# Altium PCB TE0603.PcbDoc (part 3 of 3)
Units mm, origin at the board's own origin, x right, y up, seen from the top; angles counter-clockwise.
Board outline 115 x 70 mm, 4 copper layers (L 01 (Top), L 02, L 03, L 04 (Bot)), stack 1.564 mm thick; 86 components, 166 nets, 587 pads, 211 vias.
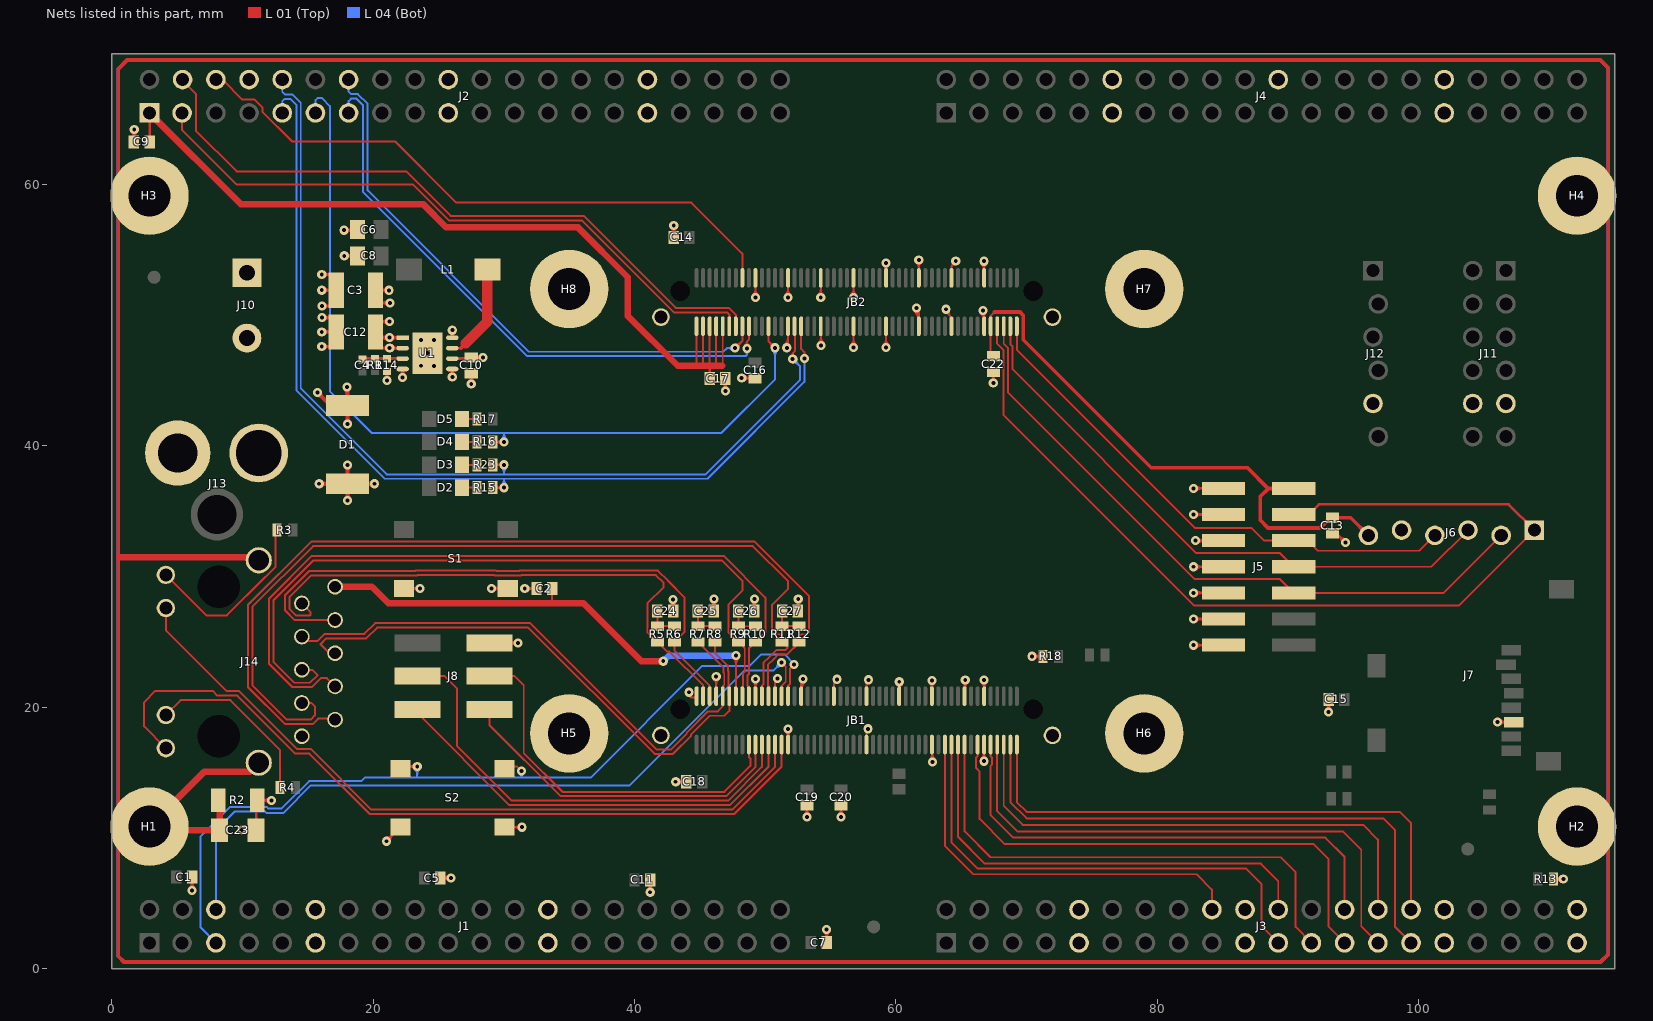
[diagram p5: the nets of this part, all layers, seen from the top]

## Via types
v1: diameter 0.7, hole 0.3, L 01 (Top) to L 04 (Bot), 211 vias

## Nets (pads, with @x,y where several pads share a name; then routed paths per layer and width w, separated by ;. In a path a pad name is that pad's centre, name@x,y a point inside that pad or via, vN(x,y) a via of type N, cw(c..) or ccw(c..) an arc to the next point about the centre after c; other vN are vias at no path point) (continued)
B2B_B3_L9_P: J2.11 JB2.24 R16.2 | length 70.9
  L 01 (Top) w0.15: R16.2@29.15,40.3 v1(30.025,40.3) ; v1@29.831,40.106 ccw(c29.361,39.636) 29.361,40.3 ccw(c29.361,40.964) v1@29.831,40.494 ; JB2.24@50.25,48.85 50.25,48.005 v1(50.752,47.502) ; v1@50.477,47.502 ccw(c49.814,47.502) 50.283,47.972 ccw(c50.752,48.441) v1@50.752,47.777
  L 04 (Bot) w0.15: J2.11@15.591,65.479 15.591,66.441 15.75,66.6 16.1,66.6 16.7,66 16.7,44.17 19.885,40.985 46.641,40.985 50.752,45.097 v1(50.752,47.502) ; v1@29.831,40.495 ccw(c29.371,40.96) 30.025,40.96 ; v1(30.025,40.3) 30.025,40.96 ; v1@30.219,40.495 cw(c30.679,40.96) 30.025,40.96 ; v1@50.558,47.308 cw(c50.089,46.838) 50.752,46.838 cw(c51.416,46.838) v1@50.947,47.308
B2B_B3_L59_N: J2.9 JB2.34 R15.2 | length 77.1
  L 01 (Top) w0.15: R15.2@29.15,36.8 v1(30.025,36.8) ; v1@29.831,36.606 ccw(c29.361,36.136) 29.361,36.8 ccw(c29.361,37.464) v1@29.831,36.994 ; JB2.34@52.75,48.85 52.75,47.425 53.003,47.172 ; v1@52.857,46.911 ccw(c52.694,47.172) 53.003,47.172 ; v1(53.003,46.677) 53.003,47.172 ; v1@53.148,46.911 cw(c53.311,47.172) 53.003,47.172
  L 04 (Bot) w0.15: J2.9@13.051,65.479 13.051,66.351 13.25,66.55 13.669,66.55 14.125,66.094 14.125,44.25 20.89,37.485 30.025,37.485 ; v1@29.831,36.994 ccw(c29.361,37.464) 30.025,37.464 ccw(c30.689,37.464) v1@30.219,36.994 ; v1(30.025,36.8) 30.025,37.485 ; v1(53.003,46.677) 53.003,44.903 45.585,37.485 30.025,37.485
B2B_B3_L59_P: J2.10 JB2.32 R23.2 | length 77.9
  L 01 (Top) w0.15: R23.2@29.15,38.55 v1(30.025,38.55) ; v1@29.831,38.356 ccw(c29.361,37.886) 29.361,38.55 ccw(c29.361,39.214) v1@29.831,38.744 ; v1@51.987,46.902 ccw(c51.903,47.083) 52.103,47.083 ; v1@52.218,46.902 cw(c52.302,47.083) 52.103,47.083 ; JB2.32@52.25,48.85 52.268,48.833 52.268,47.248 52.103,47.083 ; v1@52.103,46.753 v1(52.103,46.652) 52.098,46.652 52.05,46.7 v1@52.103,46.753 ; v1@52.103,46.753 52.103,47.083
  L 04 (Bot) w0.15: J2.10@13.051,68.019 13.051,67.089 13.25,66.89 13.81,66.89 14.465,66.235 14.465,44.39 21.031,37.825 45.444,37.825 52.65,45.031 52.65,46.105 v1(52.103,46.652) ; v1@29.831,38.356 cw(c29.361,37.886) 30.025,37.886 cw(c30.689,37.886) v1@30.219,38.356 ; 30.025,37.85 v1(30.025,38.55) ; v1@52.103,46.377 cw(c52.103,45.713) 52.572,46.183 cw(c53.041,46.652) v1@52.378,46.652
B2B_B3_L60_N: J2.14 JB2.16 | length 46.3
  L 01 (Top) w0.15: v1@47.7,47.75 ccw(c47.7,48.427) 48.178,47.948 ; v1@47.935,47.705 48.25,48.02 JB2.16@48.25,48.85 ; v1@47.975,47.475 cw(c48.626,47.475) 48.166,47.935
  L 04 (Bot) w0.15: J2.14@18.131,68.019 18.131,67.109 18.325,66.915 18.841,66.915 19.575,66.181 19.575,59.55 31.925,47.2 46.8,47.2 47.075,47.475 ; v1@47.497,47.289 ccw(c47.075,46.902) 47.075,47.475 ; v1@47.497,47.661 cw(c47.075,48.048) 47.075,47.475 ; v1@47.7,47.552 47.852,47.552 47.775,47.475 v1(47.7,47.475) 47.075,47.475
B2B_B3_L60_P: J2.13 JB2.18 | length 46.8
  L 01 (Top) w0.15: v1@48.447,47.68 ccw(c48.248,47.973) 48.602,47.973 ; v1(48.602,47.452) 48.602,47.973 ; JB2.18@48.75,48.85 48.75,48.121 48.602,47.973 ; v1@48.757,47.68 cw(c48.957,47.973) 48.602,47.973
  L 04 (Bot) w0.15: J2.13@18.131,65.479 18.131,66.381 18.325,66.575 18.7,66.575 19.235,66.04 19.235,59.409 31.784,46.86 48.51,46.86 48.602,46.952 ; v1@48.455,47.22 cw(c48.285,46.952) 48.602,46.952 ; v1(48.602,47.452) 48.602,46.952 ; v1@48.75,47.22 ccw(c48.919,46.952) 48.602,46.952
B2B_PROGB: J2.3 JB2.12 | length 50.2
  L 01 (Top) w0.15: J2.3@5.391,65.449 5.391,64.148 9.538,60 23.046,60 25.796,57.25 35.884,57.25 35.969,57.25 43.009,50.21 47.084,50.21 47.25,50.044 JB2.12@47.25,49.15 ; JB2.12@47.25,48.85 JB2.12@47.25,49.15
CCLK: J3.26 JB1.92 | length 37.8
  L 01 (Top) w0.15: JB1.92@67.25,17.05 67.25,16.235 67.355,16.13 67.355,15.62 67.25,15.515 67.25,11.75 68.975,10.025 92.85,10.025 94.331,8.544 J3.26@94.331,4.519
CSO_B: J3.25 JB1.88 | length 40.6
  L 01 (Top) w0.15: JB1.88@66.25,17.05 66.25,16.255 66.125,16.13 66.125,15.355 66.4,15.08 66.4,11.46 68.335,9.525 91.95,9.525 93.1,8.375 93.1,3.21 J3.25@94.331,1.979
EN: J1.6 JB1.27 | length 58.7
  L 01 (Top) w0.15: JB1.27@51.25,20.75 51.25,21.631 51.57,21.95 51.57,23.105 v1(51.25,23.425)
  L 04 (Bot) w0.15: J1.6@7.971,4.519 7.971,10.571 9.425,12.025 11.726,12.025 11.83,11.921 13.146,11.921 15.243,14.017 39.631,14.017 48.438,22.825 50.65,22.825 v1(51.25,23.425) ; v1@50.975,23.425 cw(c50.311,23.425) 50.781,22.956 cw(c51.25,22.486) v1@51.25,23.15
FGND: C23.1 H1.1 H2.1 H3.1 H4.1 J14.15 J14.16 R2.1 | length 758.1
  L 01 (Top) w0.3: 0.501,0.949 0.501,68.824 1.186,69.509 113.891,69.509 114.501,68.899 114.501,1.099 113.901,0.499 0.951,0.499 0.501,0.949
  L 01 (Top) w0.5: 0.596,31.475 J14.15@11.25,31.475 ; R2.1@8.15,12.9 8.25,12.8 C23.1@8.25,10.6 3.16,10.6 H1.1@2.891,10.869 7.071,15.05 10.545,15.05 J14.16@11.25,15.755
  L 04 (Bot) w0.3: 0.501,0.949 0.501,68.824 1.176,69.499 113.901,69.499 114.501,68.899 114.501,1.099 113.901,0.499 0.951,0.499 0.501,0.949
GND: C1.2 C2.1 C3.1 C5.2 C6.2 C7.2 C8.2 C9.2 C10.2 C11.2 C12.1 C13.2 C14.2 C15.2 C16.2 C17.2 C18.1 C19.1 C20.1 C22.2 C23.2 C24.2 C25.2 C26.2 C27.2 D1.2 H5.1 H6.1 H7.1 H8.1 J1.11 J1.12 J1.25 J1.26 J2.8 J2.19 J2.20 J2.31 J2.32 J3.9 J3.10 J3.19 J3.20 J3.31 J3.32 J3.39 J3.40 J4.11 J4.12 J4.22 J4.31 J4.32 J5.1 J5.3 J5.5 J5.7 J5.9 J5.11 J5.13 J6.5 J7.6 J8.2 J10.2 J11.9 J11.10 J12.5 J13.3 J14.10 JB1.1 JB1.7 JB1.19 JB1.25 JB1.30 JB1.33 JB1.43 JB1.53 JB1.54 JB1.63 JB1.73 JB1.74 JB1.83 JB1.89 JB1.90 JB1.F1 JB1.F2 JB2.19 JB2.29 JB2.30 JB2.39 JB2.40 JB2.49 JB2.50 JB2.59 JB2.60 JB2.69 JB2.70 JB2.79 JB2.80 JB2.89 JB2.90 JB2.F1 JB2.F2 R2.2 R13.2 R14.2 R18.1 S1.2 S2.2 U1.4 U1.5 U1.8 U1.9 | length 194.1
  L 01 (Top) w0.15: v1(21.025,9.75) S2.2@22.1,10.825 ; v1@21.025,10.025 ccw(c21.025,10.689) 21.494,10.219 ccw(c21.964,9.75) v1@21.3,9.75 ; S1.2@22.355,29.1 v1(23.6,29.1) ; v1@23.406,28.906 ccw(c22.936,28.436) 22.936,29.1 ccw(c22.936,29.764) v1@23.406,29.294 ; C5.2@25.125,6.925 v1(25.95,6.925) ; v1@25.756,6.731 ccw(c25.286,6.261) 25.286,6.925 ccw(c25.286,7.589) v1@25.756,7.119 ; J8.2@28.9,24.915 v1(31.09,24.915) ; v1(29.05,29.1) S1.2@30.305,29.1 ; v1@29.244,28.906 cw(c29.714,28.436) 29.714,29.1 cw(c29.714,29.764) v1@29.244,29.294 ; S2.2@30.05,10.825 v1(31.4,10.825) ; v1@30.896,24.721 ccw(c30.426,24.251) 30.426,24.915 ccw(c30.426,25.579) v1@30.896,25.109 ; v1@31.206,10.631 ccw(c30.736,10.161) 30.736,10.825 ccw(c30.736,11.489) v1@31.206,11.019 ; v1(31.6,29.075) C2.1@32.5,29.075 ; v1@31.794,28.881 cw(c32.264,28.411) 32.264,29.075 cw(c32.264,29.739) v1@31.794,29.269 ; v1(44.175,21.15) 44.054,21.15 43.944,21.04 44.01,21.04 44.3,20.75 JB1.1@44.75,20.75 ; v1@46.056,22.155 cw(c45.586,21.686) 46.25,21.686 cw(c46.914,21.686) v1@46.445,22.155 ; JB1.7@46.25,20.75 v1(46.25,22.35) ; v1@49.056,21.981 cw(c48.585,21.51) JB1.19@49.25,21.51 ; v1@49.056,51.545 ccw(c48.586,52.014) 49.25,52.014 ccw(c49.914,52.014) v1@49.445,51.545 ; JB1.19@49.25,20.75 49.25,22 v1(49.25,22.175) ; JB1.19@49.25,21.512 cw(c49.913,21.512) v1@49.444,21.981 ; v1(49.25,51.35) JB2.19@49.25,52.55 ; JB1.25@50.75,20.525 JB1.25@50.75,20.75 ; JB1.25@50.75,20.75 50.75,22 v1(50.95,22.2) ; v1@51.458,47.697 ccw(c50.753,48.402) JB2.30@51.75,48.402 ; v1@51.556,18.156 cw(c51.085,17.685) JB1.30@51.75,17.685 ; v1@51.556,51.545 ccw(c51.086,52.014) 51.75,52.014 ccw(c52.414,52.014) v1@51.945,51.545 ; v1@51.564,47.591 ccw(c51.115,48.04) 51.75,48.04 ; v1(51.653,47.502) 51.75,47.6 JB2.30@51.75,48.85 ; JB1.30@51.75,17.05 v1@51.75,18.191 ; JB1.30@51.75,17.687 cw(c52.413,17.687) v1@51.944,18.156 ; 51.75,47.93 ccw(c52.08,47.93) v1@51.847,47.697 ; v1(51.75,51.35) JB2.29@51.75,52.55 ; v1@52.683,21.957 cw(c52.521,21.795) 52.75,21.795 ; JB1.33@52.75,20.75 52.75,22.024 v1(52.878,22.151) ; JB1.33@52.75,21.18 cw(c53.849,21.18) v1@53.072,21.957 ; JB1.33@52.75,21.542 cw(c53.487,21.542) v1@52.966,22.063 ; v1@53.006,11.794 ccw(c52.536,12.264) 53.2,12.264 ccw(c53.864,12.264) v1@53.394,11.794 ; v1(53.2,11.6) C19.1@53.2,12.5 ; v1@54.056,51.545 ccw(c53.586,52.014) 54.25,52.014 ccw(c54.914,52.014) v1@54.445,51.545 ; v1@54.083,47.872 ccw(c53.68,48.275) 54.25,48.275 ; v1@54.25,47.705 JB2.40@54.25,48.85 ; 54.25,48.045 ccw(c54.646,48.045) v1@54.366,47.766 ; JB2.40@54.25,48.407 ccw(c55.008,48.407) v1@54.472,47.872 ; v1(54.25,51.35) JB2.39@54.25,52.55 ; JB1.43@55.25,20.75 55.25,21.85 55.35,21.95 55.315,21.985 55.315,21.991 55.464,22.14 v1(55.499,22.14) ; v1@55.606,11.794 ccw(c55.136,12.264) 55.8,12.264 ccw(c56.464,12.264) v1@55.994,11.794 ; v1(55.8,11.6) C20.1@55.8,12.5 ; v1@56.556,47.719 ccw(c56.085,48.19) 56.75,48.19 ; v1@56.556,51.545 ccw(c56.086,52.014) 56.75,52.014 ccw(c57.414,52.014) v1@56.945,51.545 ; v1(56.75,47.525) JB2.50@56.75,48.85 ; 56.75,48.188 ccw(c57.413,48.188) v1@56.944,47.719 ; v1(56.75,51.35) JB2.49@56.75,52.55 ; JB1.54@57.75,17.05 57.75,18.191 57.783,18.225 57.853,18.225 v1(57.853,18.351) ; JB1.53@57.75,20.75 57.75,21.849 57.903,22.001 57.929,22.001 57.929,22.071 57.903,22.097 v1(57.903,22.101) ; v1@59.056,47.719 ccw(c58.585,48.19) 59.25,48.19 ; v1@59.058,53.808 cw(c58.595,53.345) JB2.59@59.25,53.345 ; v1(59.25,47.525) JB2.60@59.25,48.85 ; 59.25,48.188 ccw(c59.913,48.188) v1@59.444,47.719 ; JB2.59@59.25,52.55 59.25,53.75 59.25,54.197 59.253,54.197 v1(59.253,54.003) ; JB2.59@59.25,53.332 cw(c59.923,53.332) v1@59.447,53.808 ; v1@60.058,21.757 cw(c59.596,21.294) JB1.63@60.25,21.294 ; JB1.63@60.25,20.75 60.25,22.025 60.325,22.1 v1@60.35,22.075 ; JB1.63@60.25,21.281 cw(c60.923,21.281) v1@60.447,21.757 ; v1(60.253,21.951) 60.253,21.947 60.275,21.925 60.327,21.925 60.378,21.976 60.374,21.976 60.374,22.075 60.477,22.075 60.503,22.101 v1@60.499,22.101 ; v1@61.381,50.356 cw(c60.489,49.464) JB2.70@61.75,49.464 ; v1@61.487,50.462 cw(c60.851,49.826) JB2.70@61.75,49.826 ; v1@61.556,54.031 cw(c61.086,53.561) 61.75,53.561 cw(c62.414,53.561) v1@61.944,54.031 ; v1(61.575,50.55) 61.75,50.375 JB2.70@61.75,49.15 ; v1@61.593,50.568 cw(c61.213,50.188) 61.75,50.188 ; JB2.70@61.75,48.85 61.75,49.975 ; JB2.69@61.75,52.55 JB2.69@61.75,52.85 v1(61.75,54.225) ; v1@62.556,21.855 cw(c62.086,21.386) 62.75,21.386 cw(c63.414,21.386) v1@62.945,21.855 ; v1@62.606,16.019 ccw(c62.256,16.369) 62.75,16.369 ; 62.75,16.247 ccw(c63.222,16.247) v1@62.888,15.913 ; JB1.74@62.75,16.609 ccw(c63.584,16.609) v1@62.994,16.019 ; JB1.74@62.75,17.05 62.75,15.958 62.8,15.908 v1(62.8,15.825) ; JB1.73@62.75,20.75 v1(62.75,22.05) ; v1@63.828,50.177 cw(c63.828,49.981) 63.967,50.12 ; v1(63.828,50.452) 63.828,50.182 63.845,50.165 63.922,50.165 64.25,49.837 JB2.80@64.25,48.85 ; v1@63.942,50.401 ccw(c64.198,50.286) 64,50.087 ; v1@64.079,50.34 ccw(c64.41,50.191) 64.153,49.933 ; JB2.79@64.25,52.55 64.25,53.75 64.451,53.95 64.575,53.95 64.578,53.953 v1(64.578,54.153) ; v1@64.33,54.034 cw(c64.135,53.941) 64.288,53.787 cw(c64.514,53.561) v1@64.549,53.879 ; v1@65.109,21.882 cw(c64.767,21.54) JB1.83@65.25,21.54 ; JB1.83@65.25,20.75 65.25,22.075 v1(65.303,22.076) ; JB1.83@65.25,21.284 cw(c66.095,21.284) v1@65.498,21.882 ; 65.25,21.647 cw(c65.733,21.647) v1@65.392,21.988 ; v1@66.459,50.158 cw(c65.755,49.454) JB2.90@66.75,49.454 ; v1@66.534,53.933 cw(c66.011,53.411) JB2.89@66.75,53.411 ; v1@66.546,16.069 ccw(c66.051,16.564) JB1.90@66.75,16.564 ; v1@66.556,21.881 cw(c66.086,21.411) 66.75,21.411 cw(c67.414,21.411) v1@66.945,21.881 ; v1@66.565,50.264 cw(c66.117,49.816) JB2.90@66.75,49.816 ; v1@66.64,54.039 cw(c66.373,53.773) 66.75,53.773 ; v1(66.653,50.352) 66.653,50.302 66.578,50.227 66.598,50.227 66.75,50.075 JB2.90@66.75,48.85 ; v1(66.728,54.128) 66.75,54.106 66.75,53.75 ; v1@66.75,15.885 JB1.90@66.75,17.05 ; JB1.90@66.75,16.514 ccw(c67.379,16.514) v1@66.934,16.069 ; JB1.89@66.75,20.75 v1(66.75,22.075) ; 66.75,49.923 cw(c67.083,49.923) v1@66.848,50.158 ; JB2.89@66.75,52.55 66.75,53.75 ; JB2.89@66.75,53.517 cw(c67.339,53.517) v1@66.923,53.933 ; v1@67.256,44.994 ccw(c66.786,45.464) 67.45,45.464 ccw(c68.114,45.464) v1@67.644,44.994 ; v1(67.45,44.8) C22.2@67.45,45.65 ; 66.75,53.749 cw(c66.885,53.749) 66.833,53.874 ccw(c66.884,53.749) 66.75,53.749 ; 66.75,53.749 ccw(c66.636,53.749) 66.663,53.861 cw(c66.636,53.749) 66.75,53.749
  L 01 (Top) w0.2: v1@1.548,64.033 cw(c1.182,63.666) C9.2@1.7,63.666 ; C9.2@1.7,63.25 1.7,64.184 v1(1.725,64.209) ; C9.2@1.7,63.546 cw(c2.389,63.546) v1@1.902,64.033 ; v1@5.973,6.152 ccw(c5.546,6.579) 6.15,6.579 ccw(c6.754,6.579) v1@6.327,6.152 ; v1(6.15,5.975) C1.2@6.15,7 ; v1(9.95,10.6) C23.2@11.05,10.6 11.05,12.8 R2.2@11.15,12.9 12.25,12.9 v1(12.226,12.876) ; v1@10.127,10.423 cw(c10.554,9.996) 10.554,10.6 cw(c10.554,11.204) v1@10.127,10.777 ; R2.2@11.563,12.9 cw(c11.563,12.213) v1@12.049,12.699 ; R2.2@11.681,12.9 ccw(c11.681,13.42) v1@12.049,13.052 ; v1(16.07,47.6) C12.1@17.1,47.6 ; v1(16.07,48.72) C12.1@17.1,48.72 ; v1(16.07,51.91) C3.1@17.1,51.91 ; v1(16.07,53.11) C3.1@17.1,53.11 ; v1(16.08,49.81) C12.1@17.11,49.81 ; v1(16.08,50.7) C3.1@17.11,50.7 ; v1@16.247,47.423 cw(c16.674,46.996) 16.674,47.6 cw(c16.674,48.204) v1@16.247,47.777 ; v1@16.247,48.543 cw(c16.674,48.116) 16.674,48.72 cw(c16.674,49.324) v1@16.247,48.897 ; v1@16.247,51.733 cw(c16.674,51.306) 16.674,51.91 cw(c16.674,52.514) v1@16.247,52.087 ; v1@16.247,52.933 cw(c16.674,52.506) 16.674,53.11 cw(c16.674,53.714) v1@16.247,53.287 ; v1@16.257,49.633 cw(c16.684,49.206) 16.684,49.81 cw(c16.684,50.414) v1@16.257,49.987 ; v1@16.257,50.523 cw(c16.684,50.096) 16.684,50.7 cw(c16.684,51.304) v1@16.257,50.877 ; v1(17.77,56.5) C6.2@18.8,56.5 ; v1(17.79,54.54) C8.2@18.82,54.54 ; v1@17.947,56.323 cw(c18.374,55.896) 18.374,56.5 cw(c18.374,57.104) v1@17.947,56.677 ; v1@17.967,54.363 cw(c18.394,53.936) 18.394,54.54 cw(c18.394,55.144) v1@17.967,54.717 ; v1@20.883,45.187 ccw(c20.456,45.614) 21.06,45.614 ccw(c21.664,45.614) v1@21.237,45.187 ; v1(21.06,45.01) R14.2@21.06,45.7 ; v1@22.083,45.397 ccw(c21.656,45.824) 22.26,45.824 ccw(c22.864,45.824) v1@22.437,45.397 ; v1(22.26,45.22) 22.26,45.32 U1.4@22.26,45.88 ; v1@25.883,45.437 ccw(c25.456,45.864) 26.06,45.864 ccw(c26.664,45.864) v1@26.237,45.437 ; v1@25.891,48.666 cw(c25.535,48.28) U1.8@26.06,48.28 ; v1(26.06,45.26) U1.5@26.06,45.88 ; v1(26.06,48.85) U1.8@26.06,48.28 ; v1@26.229,48.666 ccw(c26.585,48.28) U1.8@26.06,48.28 ; v1@27.333,44.917 ccw(c26.906,45.344) 27.51,45.344 ccw(c28.114,45.344) v1@27.687,44.917 ; v1(27.51,44.74) C10.2@27.51,45.56 ; v1@41.023,6.027 ccw(c40.596,6.454) 41.2,6.454 ccw(c41.804,6.454) v1@41.377,6.027 ; v1(41.2,5.85) C11.2@41.2,6.8 ; v1@42.773,28.073 cw(c42.346,27.646) 42.95,27.646 cw(c43.554,27.646) v1@43.127,28.073 ; v1@42.823,56.693 cw(c42.396,56.266) 43,56.266 cw(c43.604,56.266) v1@43.177,56.693 ; C24.2@42.95,27.35 v1(42.95,28.25) ; C14.2@43,55.95 v1(43,56.87) ; v1(43.15,14.3) C18.1@43.975,14.3 ; v1@43.327,14.123 cw(c43.754,13.696) 43.754,14.3 cw(c43.754,14.904) v1@43.327,14.477 ; v1@45.898,28.098 cw(c45.532,27.732) C25.2@46.05,27.732 ; C25.2@46.05,27.35 46.05,28.25 v1(46.075,28.275) ; C25.2@46.05,27.611 cw(c46.739,27.611) v1@46.252,28.098 ; v1@46.773,44.377 ccw(c46.346,44.804) 46.95,44.804 ccw(c47.554,44.804) v1@47.127,44.377 ; v1(46.95,44.2) C17.2@46.95,45.15 ; v1(48.2,45.2) 48.225,45.175 C16.2@49.225,45.175 ; v1@48.377,45.023 cw(c48.743,44.657) C16.2@48.743,45.175 ; v1@48.377,45.377 ccw(c48.864,45.864) C16.2@48.864,45.175 ; v1@48.998,28.098 cw(c48.632,27.732) C26.2@49.15,27.732 ; C26.2@49.15,27.35 49.15,28.25 v1(49.175,28.275) ; C26.2@49.15,27.611 cw(c49.839,27.611) v1@49.352,28.098 ; v1@51.59,47.565 51.527,47.502 v1(51.653,47.502) ; v1@52.348,28.098 cw(c51.982,27.732) C27.2@52.5,27.732 ; C27.2@52.5,27.35 52.5,28.25 v1(52.525,28.275) ; C27.2@52.5,27.611 cw(c53.189,27.611) v1@52.702,28.098 ; v1@54.25,47.705 v1(54.278,47.677) ; v1@54.523,2.823 cw(c54.096,2.396) 54.7,2.396 cw(c55.304,2.396) v1@54.877,2.823 ; C7.2@54.7,2 v1(54.7,3) ; v1(66.74,15.875) v1@66.75,15.885 ; v1(70.42,23.9) R18.1@71.25,23.9 ; v1@70.597,23.723 cw(c71.024,23.296) 71.024,23.9 cw(c71.024,24.504) v1@70.597,24.077 ; v1(82.775,24.75) J5.13@85.065,24.75 ; v1(82.775,26.75) J5.11@85.065,26.75 ; v1(82.775,28.75) J5.9@85.065,28.75 ; v1(82.775,30.75) J5.7@85.065,30.75 ; v1(82.775,34.75) J5.3@85.065,34.75 ; v1(82.775,36.75) J5.1@85.065,36.75 ; v1(82.91,32.75) J5.5@85.2,32.75 ; v1@82.952,24.573 cw(c83.379,24.146) 83.379,24.75 cw(c83.379,25.354) v1@82.952,24.927 ; v1@82.952,26.573 cw(c83.379,26.146) 83.379,26.75 cw(c83.379,27.354) v1@82.952,26.927 ; v1@82.952,28.573 cw(c83.379,28.146) 83.379,28.75 cw(c83.379,29.354) v1@82.952,28.927 ; v1@82.952,30.573 cw(c83.379,30.146) 83.379,30.75 cw(c83.379,31.354) v1@82.952,30.927 ; v1@82.952,34.573 cw(c83.379,34.146) 83.379,34.75 cw(c83.379,35.354) v1@82.952,34.927 ; v1@82.952,36.573 cw(c83.379,36.146) 83.379,36.75 cw(c83.379,37.354) v1@82.952,36.927 ; v1@83.087,32.573 cw(c83.514,32.146) 83.514,32.75 cw(c83.514,33.354) v1@83.087,32.927 ; v1@92.923,19.827 ccw(c92.496,20.254) 93.1,20.254 ccw(c93.704,20.254) v1@93.277,19.827 ; v1(93.1,19.65) C15.2@93.1,20.6 ; C13.2@93.4,33.3 93.7,33.3 v1(94.4,32.6) ; v1@94.15,32.6 ccw(c93.546,32.6) 93.973,33.027 ccw(c94.4,33.454) v1@94.4,32.85 ; v1(106.025,18.875) 106.035,18.865 J7.6@107.275,18.865 ; v1@106.202,18.698 cw(c106.604,18.296) J7.6@106.604,18.865 ; v1@106.202,19.052 ccw(c106.653,19.503) J7.6@106.653,18.865 ; R13.2@110.3,6.85 v1(111.06,6.85) ; v1@110.883,6.673 ccw(c110.456,6.246) 110.456,6.85 ccw(c110.456,7.454) v1@110.883,7.027
  L 01 (Top) w0.3: v1(15.875,37.1) D1.2@18.05,37.1 v1(18.05,38.525) ; v1@16.016,36.959 cw(c16.358,36.617) 16.358,37.1 cw(c16.358,37.583) v1@16.016,37.241 ; v1@17.909,35.966 ccw(c17.566,36.309) D1.2@18.051,36.309 ; v1@17.909,38.384 cw(c17.567,38.042) 18.05,38.042 cw(c18.533,38.042) v1@18.191,38.384 ; v1@18.05,35.676 v1(18.05,35.825) ; v1@18.051,35.675 D1.2@18.05,37.1 v1(20.1,37.1) ; D1.2@18.051,36.307 ccw(c18.532,36.307) v1@18.191,35.966 ; v1@19.959,36.959 ccw(c19.617,36.617) 19.617,37.1 ccw(c19.617,37.583) v1@19.959,37.241
  L 04 (Bot) w0.15: v1@21,9.75 v1(21.025,9.75) ; v1(23.6,29.1) v1@23.637,29.137 ; v1(25.95,6.925) v1@26,6.975 ; v1@29.025,29.075 v1(29.05,29.1) ; v1(31.09,24.915) v1@31.145,24.97 ; v1(31.4,10.825) v1@31.425,10.8 ; v1@63.775,50.225 63.777,50.227 63.828,50.227 v1(63.828,50.452) ; v1@66.663,53.861 cw(c66.636,53.749) 66.75,53.749 ; v1(66.728,54.128) 66.75,54.106 66.75,53.75 ; 66.747,53.753 66.75,53.75 ; v1@66.833,53.873 ccw(c66.884,53.749) 66.75,53.749
  L 04 (Bot) w0.2: v1@43.125,14.275 v1(43.15,14.3)
  L 04 (Bot) w0.3: v1@15.825,37.05 v1(15.875,37.1)
  other v1: 51.75,18.35 24.66,46.12 23.66,46.13 24.16,47.09 23.66,48.1 24.66,48.11
HSWAPEN: J2.4 JB2.14 | length 52.6
  L 01 (Top) w0.15: J2.4@5.391,67.979 6.441,66.93 6.441,64.119 9.56,61 22.527,61 25.937,57.59 36.11,57.59 43.15,50.55 47.037,50.55 47.225,50.55 47.75,50.025 JB2.14@47.75,49.15 JB2.14@47.75,48.85
INIT: J1.5 JB1.29 S2.1 | length 69.5
  L 01 (Top) w0.15: S2.1@22.1,15.475 v1(23.375,15.475) ; v1@23.181,15.281 ccw(c22.711,14.811) 22.711,15.475 ccw(c22.711,16.139) v1@23.181,15.669 ; S2.1@30.05,15.475 31,15.475 v1(31.35,15.125) ; JB1.29@51.75,20.75 51.75,21.65 51.91,21.809 51.91,22.985 v1(52.2,23.275)
  L 04 (Bot) w0.15: J1.5@7.971,1.979 6.8,3.15 6.8,10.125 9.04,12.365 11.866,12.365 11.971,12.261 13.005,12.261 15.102,14.357 19.1,14.357 19.368,14.625 23.35,14.625 ; v1@23.181,15.281 cw(c22.711,14.811) 23.375,14.811 cw(c24.039,14.811) v1@23.569,15.281 ; v1(23.375,15.475) 23.375,14.65 23.35,14.625 ; v1@31.237,14.874 cw(c31.159,14.7) 31.35,14.7 ; v1(31.35,15.125) 31.35,14.7 ; v1@31.463,14.874 ccw(c31.541,14.7) 31.35,14.7 ; v1@52.2,23.345 51.505,24.04 49.69,24.04 48.815,23.165 45.19,23.165 36.65,14.625 31.275,14.625 ; 23.35,14.625 31.275,14.625 ; 31.275,14.625 31.35,14.7
MISO: J3.27 JB1.94 | length 41.7
  L 01 (Top) w0.15: JB1.94@67.75,17.05 67.75,12.05 69.3,10.5 94.2,10.5 95.6,9.1 95.6,3.25 J3.27@96.871,1.979
MISO2: J3.30 JB1.100 | length 41.7
  L 01 (Top) w0.15: JB1.100@69.25,17.05 69.25,12.75 70,12 98.55,12 99.411,11.139 J3.30@99.411,4.519
MISO3: J3.29 JB1.98 | length 43.8
  L 01 (Top) w0.15: JB1.98@68.75,17.05 68.75,12.75 70,11.5 97.3,11.5 98.2,10.6 98.2,3.19 J3.29@99.411,1.979
MOSI: J3.28 JB1.96 | length 39.6
  L 01 (Top) w0.15: JB1.96@68.25,17.05 68.25,12.45 69.7,11 95.75,11 96.871,9.879 J3.28@96.871,4.519
NetC4_2: C4.2 R1.2 R14.1 U1.3 | length 3.1
  L 01 (Top) w0.2: C4.2@19.21,46.64 19.25,46.68 U1.3@22.26,46.68
NetC24_1: C24.1 R5.2 R6.2 | length 2.4
  L 01 (Top) w0.15: C24.1@41.75,27.35 R5.2@41.75,26.201 R6.2@43.05,26.201
NetC25_1: C25.1 R7.2 R8.2 | length 2.4
  L 01 (Top) w0.15: C25.1@44.85,27.35 R7.2@44.85,26.201 R8.2@46.15,26.201
NetC26_1: C26.1 R9.2 R10.2 | length 2.5
  L 01 (Top) w0.15: C26.1@47.95,27.35 R9.2@47.95,26.2 R10.2@49.25,26.2
NetC27_1: C27.1 R11.2 R12.2 | length 2.4
  L 01 (Top) w0.15: C27.1@51.3,27.35 R11.2@51.3,26.201 R12.2@52.6,26.201
NetD2_K: D2.K R15.1 | length 1.2
  L 01 (Top) w0.15: D2.K@26.8,36.8 R15.1@27.95,36.8
NetD3_K: D3.K R23.1 | length 1.2
  L 01 (Top) w0.15: D3.K@26.8,38.55 R23.1@27.95,38.55
NetD4_K: D4.K R16.1 | length 1.2
  L 01 (Top) w0.15: D4.K@26.8,40.3 R16.1@27.95,40.3
NetD5_K: D5.K R17.1 | length 1.2
  L 01 (Top) w0.15: D5.K@26.8,42.05 R17.1@27.95,42.05
NetJ14_11: J14.11 R3.1 | length 14.1
  L 01 (Top) w0.15: J14.11@4.14,30.13 7.245,27.025 8.813,27.025 11.768,29.98 11.774,29.98 12.515,30.721 12.515,33.415 R3.1@12.65,33.55
NetJ14_13: J14.13 R4.1 | length 13.7
  L 01 (Top) w0.15: J14.13@4.14,19.41 5.28,20.55 9.075,20.55 12.875,16.75 R4.1@12.875,13.85
NetL1_1: L1.1 U1.7 | length 7.5
  L 01 (Top) w0.2: U1.7@26.06,47.48 26.72,47.48
  L 01 (Top) w0.3: 26.72,47.48 27.1,47.86
  L 01 (Top) w0.8: 27.1,47.86 28.75,49.51 L1.1@28.75,53.49
PFI: J2.6 JB2.15 | length 47.6
  L 01 (Top) w0.15: J2.6@8.481,68.019 10.006,66.494 10.931,66.494 11.526,65.9 11.526,65.569 13.81,63.285 21.684,63.285 26.359,58.61 44.346,58.61 48.25,54.706 JB2.15@48.25,52.55
PHY_AVDD: C2.2 J14.1 JB1.13 | length 38.9
  L 01 (Top) w0.15: 33.7,27.975 C2.2@33.7,29.075 ; v1@47.581,23.756 cw(c47.171,23.346) 47.75,23.346 ; JB1.13@47.75,20.75 v1@47.75,23.95 ; 47.75,23.226 cw(c48.499,23.226) v1@47.969,23.756 ; 47.75,23.588 cw(c48.137,23.588) v1@47.863,23.862
  L 01 (Top) w0.5: J14.1@17.09,29.215 19.91,29.215 21.15,27.975 33.7,27.975 36.075,27.975 40.525,23.525 v1(42.2,23.525)
  L 04 (Bot) w0.5: v1(42.2,23.525) 42.625,23.95 v1(47.775,23.95)
PHY_DUP: J8.5 JB1.24 | length 32.9
  L 01 (Top) w0.15: J8.5@23.4,19.835 23.4,19.525 30.41,12.515 47.302,12.515 50.25,15.463 JB1.24@50.25,17.05
PHY_L10: J8.4 JB1.18 | length 29.1
  L 01 (Top) w0.15: J8.4@28.9,22.375 30.825,22.375 31.525,21.675 31.525,16.5 34.49,13.535 46.88,13.535 48.865,15.52 48.865,16.08 48.75,16.194 JB1.18@48.75,17.05
PHY_L100: J8.6 JB1.20 | length 26.3
  L 01 (Top) w0.15: J8.6@28.9,19.835 28.9,18.644 34.349,13.195 47.021,13.195 49.25,15.425 JB1.20@49.25,17.05
PHY_L1000: J8.3 JB1.22 | length 35.5
  L 01 (Top) w0.15: J8.3@23.4,22.375 25.475,22.375 26.425,21.425 26.425,17.025 30.595,12.855 47.161,12.855 49.75,15.444 JB1.22@49.75,17.05
PHY_LED_RX: J14.14 JB1.28 | length 60.3
  L 01 (Top) w0.15: J14.14@4.14,16.87 2.475,18.535 2.475,20.375 3.35,21.25 7.725,21.25 8.085,20.89 9.61,20.89 14.047,16.453 15.117,16.453 19.734,11.835 47.617,11.835 51.25,15.469 JB1.28@51.25,17.05
PHY_LED_TX: J14.12 JB1.26 | length 57
  L 01 (Top) w0.15: J14.12@4.14,27.59 4.14,25.885 8.795,21.23 9.751,21.23 14.188,16.793 15.257,16.793 19.875,12.175 47.476,12.175 50.75,15.449 JB1.26@50.75,17.05
PHY_MDI0_N: J14.3 JB1.5 R6.1 | length 47
  L 01 (Top) w0.15: J14.3@16.805,26.96 J14.3@17.09,26.675 13.994,26.675 13.26,27.409 13.26,28.56 15.135,30.435 23.24,30.435 23.255,30.45 29.405,30.45 29.42,30.435 31.19,30.435 31.205,30.45 41.781,30.45 42.565,29.666 42.565,29.66 43.815,28.41 43.815,25.741 43.075,25.001 R6.1@43.05,25.001 43.05,24.35 45.75,21.65 JB1.5@45.75,20.75
PHY_MDI0_P: J14.2 JB1.3 R5.1 | length 44.6
  L 01 (Top) w0.15: J14.2@14.55,27.945 15.2,27.295 15.2,27.05 15.165,27.015 14.135,27.015 13.6,27.55 13.6,28.419 15.276,30.095 23.381,30.095 23.396,30.11 29.264,30.11 29.279,30.095 31.331,30.095 31.346,30.11 41.64,30.11 42.225,29.525 42.225,29.2 40.985,27.96 40.985,25.741 41.725,25.001 R5.1@41.75,25.001 ; R5.1@41.75,24.986 R5.1@41.75,25.001 ; JB1.3@45.25,20.75 45.25,21.669 42.669,24.25 42.501,24.25 R5.1@41.75,25.001
PHY_MDI1_N: J14.5 JB1.11 R8.1 | length 44.6
  L 01 (Top) w0.15: J14.5@16.89,24.335 J14.5@17.09,24.135 16.665,24.135 15.975,24.825 16.425,25.275 19.475,25.275 20.3,26.1 31.865,26.1 41.534,16.431 42.944,16.431 44.335,17.822 44.335,17.922 45.763,19.35 46.875,19.35 47.25,19.725 JB1.11@47.25,20.85 ; R8.1@46.15,25.001 46.15,24.181 47.15,23.181 47.15,22.801 47.205,22.745 47.205,22.176 47.205,20.895 JB1.11@47.25,20.85
PHY_MDI1_P: J14.4 JB1.9 R7.1 | length 44.3
  L 01 (Top) w0.15: J14.4@14.72,25.405 J14.4@14.55,25.405 14.89,25.065 15.735,25.065 16.284,25.615 19.334,25.615 20.159,26.44 32.006,26.44 41.675,16.771 42.803,16.771 43.995,17.962 43.995,18.063 45.622,19.69 46.377,19.69 46.75,20.063 46.75,21.6 46.81,21.66 46.865,21.715 46.865,22.605 46.81,22.66 46.81,23.041 R7.1@44.85,25.001
PHY_MDI2_N: J14.7 JB1.17 R10.1 | length 60.2
  L 01 (Top) w0.15: J14.7@17.09,21.595 16.46,22.225 16,22.225 15.31,21.535 13.834,21.535 12.035,23.334 12.035,28.31 15.3,31.575 46.831,31.575 50.015,28.391 50.015,25.74 49.275,25 R10.1@49.25,25 48.775,24.525 48.775,22.57 48.635,22.43 48.635,21.92 ; 48.635,21.92 48.635,21.696 48.75,21.581 JB1.17@48.75,20.75
PHY_MDI2_P: J14.6 JB1.15 R9.1 | length 58.1
  L 01 (Top) w0.15: J14.6@14.55,22.865 15.36,22.865 15.76,22.465 15.169,21.875 13.975,21.875 12.375,23.475 12.375,28.169 15.441,31.235 46.69,31.235 48.25,29.675 48.25,28.925 47.185,27.86 47.185,25.74 47.925,25 R9.1@47.95,25 48.435,24.515 48.435,22.711 48.295,22.571 48.295,21.779 48.295,21.626 48.25,21.581 JB1.15@48.25,20.75
PHY_MDI3_N: J14.9 JB1.23 R12.1 | length 70.4
  L 01 (Top) w0.15: J14.9@17.09,19.055 17.01,19.135 15.79,19.135 15.366,18.71 13.265,18.71 10.425,21.55 10.425,27.825 15.275,32.675 49.2,32.675 53.365,28.51 53.365,25.741 53.21,25.586 52.754,25.586 52.6,25.432 R12.1@52.6,25.001 ; JB1.23@50.17,21.076 50.25,21.156 50.25,21.65 50.205,21.695 50.205,23.249 50.635,23.679 50.995,24.04 51.684,24.04 R12.1@52.6,24.956
PHY_MDI3_P: J14.8 JB1.21 R11.1 | length 68.9
  L 01 (Top) w0.15: J14.8@14.55,20.325 15.3,20.325 15.55,20.075 15.55,19.375 15.225,19.05 13.406,19.05 10.765,21.691 10.765,27.684 15.416,32.335 49.059,32.335 51.75,29.644 51.75,29.075 50.535,27.86 50.535,25.741 50.69,25.586 51.146,25.586 51.3,25.432 R11.1@51.3,25.001 51.701,24.6 51.725,24.6 51.725,24.562 51.543,24.38 50.854,24.38 50.295,23.821 ; JB1.21@49.83,21.076 49.75,21.156 49.75,21.63 49.865,21.746 49.865,23.39 50.295,23.82
RFUSE: J3.23 JB1.84 | length 39.1
  L 01 (Top) w0.15: JB1.84@65.25,17.05 65.25,10.509 67.235,8.525 89.425,8.525 90.575,7.375 90.575,3.195 J3.23@91.791,1.979
SUSPEND: J3.18 JB1.78 | length 31
  L 01 (Top) w0.15: JB1.78@63.75,17.05 63.755,17.045 63.755,15.429 63.75,15.425 63.75,9.406 65.931,7.225 83,7.225 84.171,6.054 J3.18@84.171,4.519
TCK: J5.6 J6.4 JB2.100 | length 40.3
  L 01 (Top) w0.15: JB2.100@69.25,48.85 69.25,47.35 82.875,33.725 87.2,33.725 88.175,32.75 J5.6@90.435,32.75 91.5,32.75 92.275,31.975 100.055,31.975 J6.4@101.23,33.15
TDI: J5.10 J6.2 JB2.96 | length 50.8
  L 01 (Top) w0.15: JB2.96@68.25,48.85 68.25,47.806 68.565,47.491 68.565,44.09 82.855,29.8 89.385,29.8 J5.10@90.435,28.75 101.91,28.75 J6.2@106.31,33.15
TDO: J5.8 J6.3 JB2.98 | length 45.3
  L 01 (Top) w0.15: JB2.98@68.75,48.85 68.75,47.786 68.905,47.632 68.905,45.885 82.99,31.8 89.385,31.8 J5.8@90.435,30.75 100.97,30.75 J6.3@103.77,33.55
TMS: J5.4 J6.1 JB2.94 | length 75.3
  L 01 (Top) w0.15: JB2.94@67.75,48.85 67.75,47.825 68.225,47.35 68.225,42.375 82.825,27.775 103.075,27.775 J6.1@108.85,33.55
  L 01 (Top) w0.2: J5.4@90.435,34.75 91.575,34.75 92.35,35.525 106.875,35.525 J6.1@108.85,33.55
VBATT: J3.21 JB1.80 | length 37.4
  L 01 (Top) w0.15: JB1.80@64.25,17.05 64.25,9.674 66.275,7.65 86.8,7.65 87.981,6.469 87.981,3.249 J3.21@89.251,1.979
VCCAUX: C13.1 C22.1 J5.2 J6.6 JB2.92 | length 45.3
  L 01 (Top) w0.15: 67.25,49.943 67.547,50.24 ; 67.25,49.943 67.25,47.05 C22.1@67.45,46.85
  L 01 (Top) w0.3: 67.547,50.24 69.485,50.24 69.74,49.985 69.74,48.117 79.532,38.325 86.9,38.325 88.475,36.75 88.5,36.75 ; J5.2@90.435,36.75 88.5,36.75 ; J6.6@96.15,33.15 94.8,34.5 C13.1@93.4,34.5 93.219,34.5 92.444,33.725 88.475,33.725 87.875,34.325 87.875,36.125 88.5,36.75
VCCIO0: C9.1 C17.1 J2.1 JB2.2 JB2.4 JB2.6 JB2.8 JB2.10 | length 70.6
  L 01 (Top) w0.15: JB2.2@44.75,48.85 44.75,46.2 44.825,46.125 ; 45.2,46.125 45.25,46.175 JB2.4@45.25,48.85 ; 45.75,46.1 45.75,46.125 45.75,46.15 ; JB2.6@45.75,48.85 45.75,46.15 ; 45.775,46.125 45.75,46.15 ; JB2.8@46.25,48.85 46.25,46.15 46.275,46.125 ; 46.75,46.1 JB2.10@46.75,48.85
  L 01 (Top) w0.2: J2.1@2.891,65.479 2.9,65.47 C9.1@2.9,63.25 ; C17.1@45.75,45.15 45.75,46.1 45.775,46.125
  L 01 (Top) w0.5: J2.1@2.9,65.47 9.87,58.5 23.818,58.5 25.602,56.716 35.675,56.716 39.49,52.901 39.49,49.935 43.3,46.125 44.825,46.125 45.2,46.125 45.75,46.125 45.775,46.125 46.275,46.125 46.725,46.125
VFS: J3.22 JB1.82 | length 35.1
  L 01 (Top) w0.15: JB1.82@64.75,17.05 64.75,10.08 66.795,8.035 87.915,8.035 89.251,6.699 J3.22@89.251,4.519
VSUP: C3.2 C10.1 C12.2 D1.1 J10.1 J13.1 U1.1 U1.2 U1.6 | length 25.2
  L 01 (Top) w0.2: C12.2@20.18,48.71 20.18,47.99 C12.2@20.68,47.49 ; C3.2@20.18,51.91 20.19,51.9 v1(21.22,51.9) ; C12.2@20.23,49.51 v1(21.26,49.51) ; C3.2@20.25,50.94 v1(21.28,50.94) ; v1@21.043,51.723 ccw(c20.616,51.296) 20.616,51.9 ccw(c20.616,52.504) v1@21.043,52.077 ; v1@21.083,49.333 ccw(c20.656,48.906) 20.656,49.51 ccw(c20.656,50.114) v1@21.083,49.687 ; v1@21.09,47.316 ccw(c20.68,46.919) C12.2@20.68,47.49 ; v1@21.09,47.664 cw(c20.68,48.061) C12.2@20.68,47.49 ; v1@21.103,50.763 ccw(c20.676,50.336) 20.676,50.94 ccw(c20.676,51.544) v1@21.103,51.117 ; v1(21.25,48.28) U1.1@22.26,48.28 ; v1@21.27,47.48 U1.2@22.26,47.48 ; v1(21.27,47.49) C12.2@20.68,47.49 ; v1@21.427,48.103 cw(c21.854,47.676) 21.854,48.28 cw(c21.854,48.884) v1@21.427,48.457 ; v1@21.447,47.313 cw(c21.85,46.91) U1.2@21.85,47.48 ; v1@21.447,47.667 ccw(c21.897,48.117) U1.2@21.897,47.48 ; U1.6@26.06,46.68 C10.1@27.43,46.68
  L 01 (Top) w0.3: v1@15.75,43.88 cw(c15.75,43.397) 16.091,43.739 cw(c16.433,44.08) v1@15.95,44.08 ; v1(15.75,44.08) D1.1@16.73,43.1 ; D1.1@16.68,43.1 D1.1@16.73,43.1 ; v1@17.859,44.359 cw(c17.396,43.896) D1.1@18.05,43.896 ; v1@17.909,41.816 ccw(c17.568,42.158) 18.051,42.158 ccw(c18.533,42.158) v1@18.192,41.816 ; v1(18,44.5) 18.05,44.45 D1.1@18.05,43.1 D1.1@16.73,43.1 ; 18.05,44.138 cw(c18.362,44.138) v1@18.141,44.359 ; v1(18.051,41.675) D1.1@18.05,43.1 ; C12.2@20.61,48.28 v1(21.25,48.28) ; v1@21.109,48.139 ccw(c20.767,47.797) 20.767,48.28 ccw(c20.767,48.763) v1@21.109,48.421 ; C10.1@27.43,46.68 C10.1@27.51,46.76 v1(28.41,46.76) ; v1@28.269,46.619 ccw(c27.927,46.277) 27.927,46.76 ccw(c27.927,47.243) v1@28.269,46.901
pads on no net: C21.1 C21.2 J5.12 J5.14 J7.9 J7.10 J13.2 J14.H1 J14.H2 JB1.64 JB1.H1 JB1.H2 JB2.H1 JB2.H2 PM1.0 PM2.0 PM3.0
copper on no net: | length 88
  L 01 (Top) w0.15: 83.95,15.825 83.95,17.825 92.95,17.825 92.95,15.825 83.95,15.825
  L 02 w0.15: 83.95,15.825 92.95,15.825 92.95,17.825 83.95,17.825 83.95,15.825
  L 03 w0.15: 83.95,15.825 92.95,15.825 92.95,17.825 83.95,17.825 83.95,15.825
  L 04 (Bot) w0.15: 83.95,15.825 92.95,15.825 92.95,17.825 83.95,17.825 83.95,15.825

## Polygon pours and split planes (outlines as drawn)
GND on L 02 "GND" (solid, remove dead copper, pour order 1004): -1.375,-1.275 -0.55,-0.45 117.2,-0.45 117.2,69.725 114.975,71.95 114.725,71.7 -2.6,71.7
3.3V on L 03 "3V3" (solid, remove dead copper, pour order 1001): 20,70.5 20,64.5 28.5,56 46.5,56 46.5,52.5 51.5,47.5 53.5,47.5 53.5,40 116.5,40 117,39.5 117,25.5 56.275,25.475 49.45,18.675 49.45,14.925 47.9,13.375 13.35,13.35 6,6 6,-1 -2,-1 -1.5,-0.5 -1.5,70.5
GND on L 03 "GND" (solid, remove dead copper, pour order 1003): 6.5,-1 6.5,6 11.5,11 15,14.5 36,14.5 36.5,14.5 43,21 47,25 56,25 66.2,25 101.5,25 118,25 118.5,24.5 118.5,-2
GND on L 03 "GND" (solid, remove dead copper, pour order 1002): 11.5,71 11.5,61.5 14,59 18,55 18,42 18,39.5 21.5,36 47,36 47.3,36 52,40.7 52.2,40.5 118,40.5 118,71 117,72
VSUP on L 03 "VSUP" (solid, remove dead copper, pour order 1000): 9,37 15.5,37 18.5,40 18.5,46 30,46 30,47 26,51 22,51 22,53 20,55 9,55

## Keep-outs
Keep-Out Layer:
  lines w0.3: 0.001,9.175 0.001,-0.001 115.001,-0.001 115.001,9.175 ; 0.001,12.55 0.001,57.45 ; 0.001,60.825 0.001,69.999 115.001,69.999 115.001,60.825 ; 115.001,12.55 115.001,57.225 ; 115.001,57.275 115.001,57.45

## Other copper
L 01 (Top):
  text "L1" at 84.45,16.325 h1
L 02:
  text "L2" at 86.45,16.325 h1
L 03:
  text "L3" at 88.45,16.325 h1
L 04 (Bot):
  text "L4" at 92.45,16.325 h1

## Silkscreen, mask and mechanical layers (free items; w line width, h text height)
Boardumrandung:
  the board outline again, w0.01
Print-Top-GM3:
  text "2" at 61.101,67.499 h1.5
  text "1" at 0.701,64.799 h1.5
  text "1" at 61.375,64.775 h1.5
  text "J2" at 24.569,62.031 h1.5
  text "J4" at 87.901,61.699 h1.5
  text "J11" at 104.6,56.6 h1.5
  text "V+" at 6.95,56.375 h1.5
  text "J12" at 95.9,55.4 h1.5
  text "JB2" at 70.85,54.825 h1.5
  text "1" at 41.35,54.575 h1.5
  text "J1" at 14.875,54.25 h1.5
  text "1" at 93.345,52.705 h1.5
  text "1" at 101.6,52.705 h1.5
  text "GND" at 1.5,47.4 h1.5
  text "2" at 42.875,46.025 h1.5
  text "Center+" at 0.625,44.7 h1
  text "J5" at 86.6,42.8 h1.5
  text "D5" at 30.8,41.5 h1
  text "D4" at 30.8,39.8 h1
  text "D3" at 30.8,38 h1
  text "D2" at 30.8,36.3 h1
  text "1" at 81.2,36.3 h1.5
  text "W" at 68.25,35.125 h10
  text "VREF" at 96.6,35 h1 r90
  text "GND" at 99.2,35 h1 r90
  text "TCK" at 101.6,35 h1 r90
  text "TDO" at 104.2,35 h1 r90
  text "TDI" at 106.9,35 h1 r90
  text "TMS" at 109.3,35 h1 r90
  text "S1" at 31.65,32.9 h1.5
  text "J13" at 1.3,32.8 h1.5
  text "J6" at 110.8,32.6 h1.5
  text "www.trenz-electronic.de" at 43.05,32.5 h1.5
  text "Reset" at 30.6,30.75 h1.5
  text "TE0603-02 / 2011" at 48.4,30 h1.5
  text "1" at 19.7,24.29 h1.5
  text "J8" at 32.9,23.9 h1.5
  text "1" at 39.7,20.625 h1.5
  text "2" at 39.4,14.9 h1.5
  text "J14" at 15.625,12.95 h1.5
  text "JB1" at 73,12.92 h1.5
  text "J7" at 100.2,12.4 h1.5
  text "S2" at 30.2,12.3 h1.5
  text "Init" at 32,10.15 h1.5
  text "J3" at 86.901,7.099 h1.5
  text "J1" at 26.95,6.6 h1.5
  text "2" at 60.701,3.799 h1.5
  text "1" at 0.501,1.199 h1.5
  text "1" at 60.901,1.099 h1.5
Mechanical 6:
  lines w0.01: 32,15 82,15 82,55 32,55 32,15
13TopAssy:
  text "PMOD" at 91.44,55.245 h1
  text "PMOD" at 101.6,55.245 h1
  text "1" at 93.726,52.705 h1.5
  text "1" at 101.981,52.705 h1.5
  text "2" at 93.472,50.165 h1.5
  text "2" at 101.727,50.165 h1.5
  text "3" at 93.472,47.625 h1.5
  text "3" at 101.727,47.625 h1.5
  text "4" at 93.472,45.085 h1.5
  text "4" at 101.727,45.085 h1.5
  text "5" at 93.472,42.545 h1.5
  text "5" at 101.727,42.545 h1.5
  text "6" at 93.472,40.005 h1.5
  text "6" at 101.727,40.005 h1.5

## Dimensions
115.001,69.999 to 112.111,59.129 on Dimension
115.001,-0.001 to 79,52 on Dimension
115.001,-0.001 to 79,18 on Dimension
115.001,-0.001 to 112.111,10.869 on Dimension
0.001,-0.001 to 79,18 on Dimension
0.001,-0.001 to 35,18 on Dimension
115.001,-0.001 to 112.111,10.869 on Dimension
0.001,-0.001 to 63.851,1.979 on Dimension
0.001,-0.001 to 2.891,10.869 on Dimension
35,52 to 57,52 on Drill Drawing
35,18 to 35,18 on Drill Drawing
0.001,-0.001 to 115.001,-0.001 on Dimension
115.001,-0.001 to 115.001,69.999 on Dimension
